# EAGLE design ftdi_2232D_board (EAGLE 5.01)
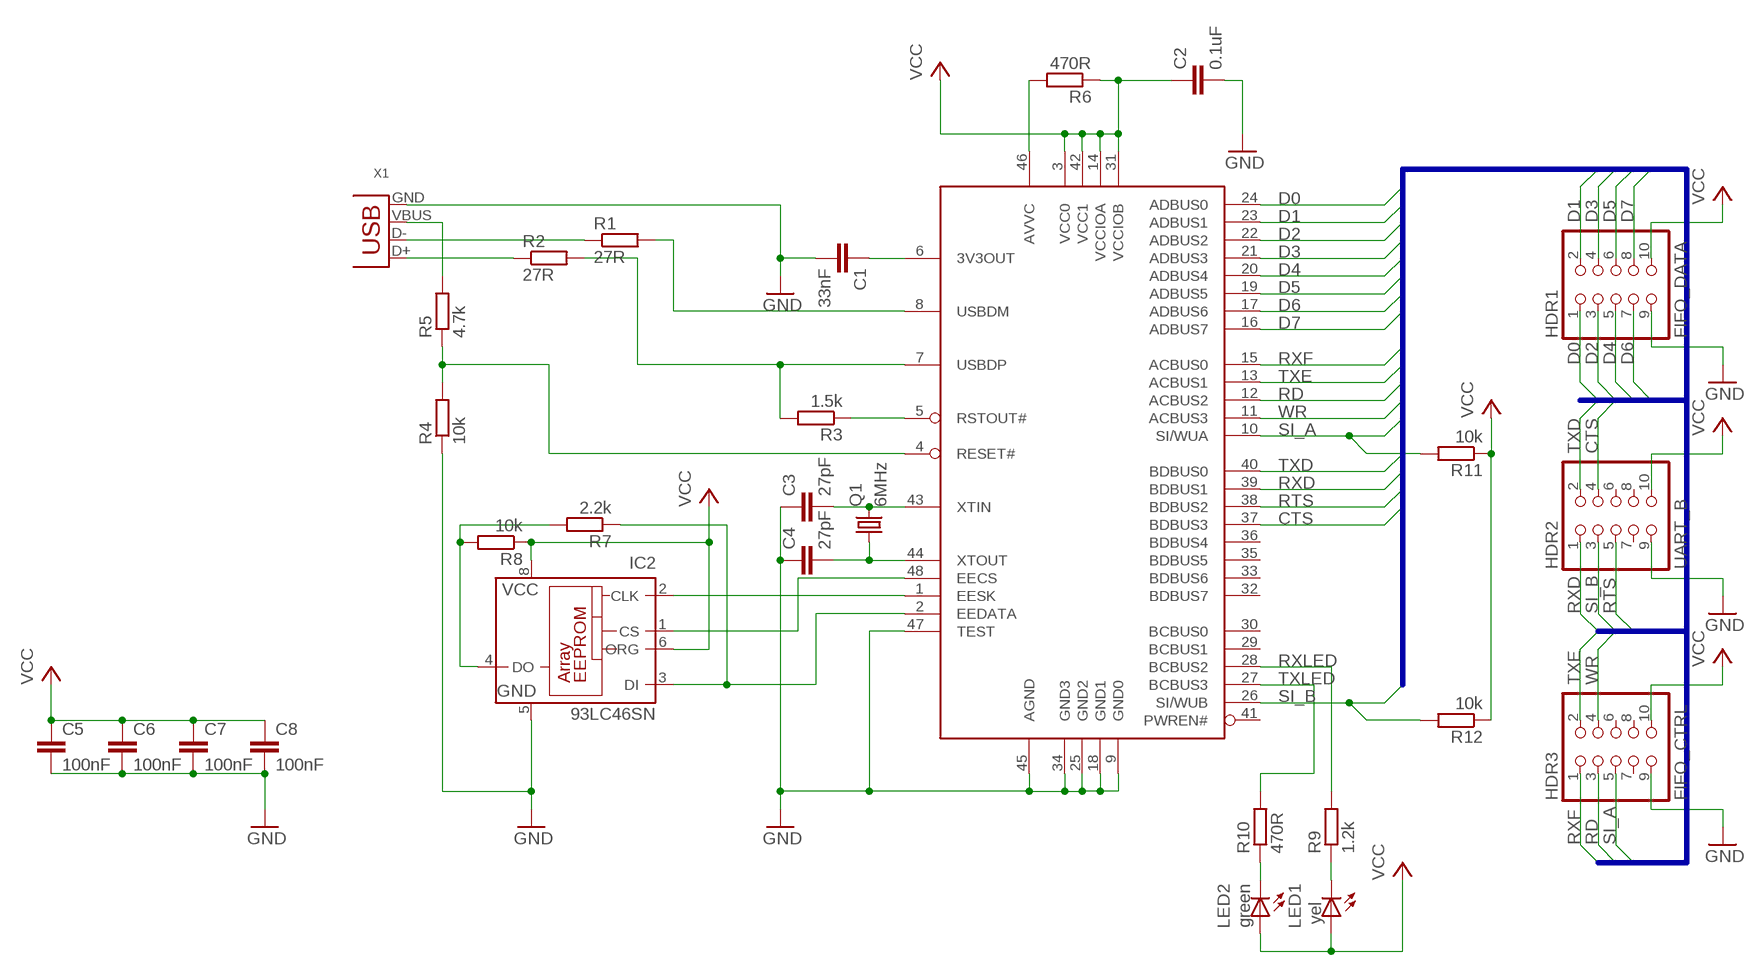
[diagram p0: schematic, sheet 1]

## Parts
C1  33nF  C-EUC0805  [C0805]
C2  0.1uF  C-EUC0805  [C0805]
C3  27pF  C-EUC0805  [C0805]
C4  27pF  C-EUC0805  [C0805]
C5  100nF  C-EUC0805  [C0805]
C6  100nF  C-EUC0805  [C0805]
C7  100nF  C-EUC0805  [C0805]
C8  100nF  C-EUC0805  [C0805]
HDR1  FIFO_DATA  PINHD-2X5  [2X05]
HDR2  UART_B  PINHD-2X5  [2X05]
HDR3  FIFO_CTRL  PINHD-2X5  [2X05]
IC1  FT2232D  FT2232L  [LQFP48]
IC2  93LC46SN  [SO-08]
LED1  yel  LEDSMT1206  [1206]
LED2  green  LEDSMT1206  [1206]
Q1  6MHz  CRYSTALHC49U70  [HC49U70]
R1  27R  R-EU_R0805  [R0805]
R2  27R  R-EU_R0805  [R0805]
R3  1.5k  R-EU_R0805  [R0805]
R4  10k  R-EU_R0805  [R0805]
R5  4.7k  R-EU_R0805  [R0805]
R6  470R  R-EU_R0805  [R0805]
R7  2.2k  R-EU_R0805  [R0805]
R8  10k  R-EU_R0805  [R0805]
R9  1.2k  R-EU_R0805  [R0805]
R10  470R  R-EU_R0805  [R0805]
R11  10k  R-EU_R0805  [R0805]
R12  10k  R-EU_R0805  [R0805]
X1  USBCON  USB-MB-S  [USB-MB-S]

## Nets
3V3OUT: C1.1 IC1.6(3V3OUT)
CTS: HDR2.4 IC1.37(BDBUS3)
D0: HDR1.1 IC1.24(ADBUS0)
D1: HDR1.2 IC1.23(ADBUS1)
D2: HDR1.3 IC1.22(ADBUS2)
D3: HDR1.4 IC1.21(ADBUS3)
D4: HDR1.5 IC1.20(ADBUS4)
D5: HDR1.6 IC1.19(ADBUS5)
D6: HDR1.7 IC1.17(ADBUS6)
D7: HDR1.8 IC1.16(ADBUS7)
D+: R2.1 X1.D+
D-: R1.1 X1.D-
EE_DOUT: IC2.4(DO) R7.2 R8.2
EECS: IC1.48(EECS) IC2.1(CS)
EEDATA: IC1.2(EEDATA) IC2.3(DI) R7.1
EESK: IC1.1(EESK) IC2.2(CLK)
GND: C1.2 C2.2 C3.1 C4.1 C5.2 C6.2 C7.2 C8.2 HDR1.9 HDR2.9 HDR3.9 IC1.9(GND0) IC1.18(GND1) IC1.25(GND2) IC1.34(GND3) IC1.45(AGND) IC1.47(TEST) IC2.5(GND) R4.1 X1.GND
N$12: IC1.46(AVVC) R6.2
N$13: LED1.C R9.1
N$14: LED2.C R10.1
RD: HDR3.3 IC1.12(ACBUS2)
RESET: IC1.4(RESET#) R4.2 R5.1
RSTOUT: IC1.5(RSTOUT#) R3.1
RTS: HDR2.5 IC1.38(BDBUS2)
RXD: HDR2.1 IC1.39(BDBUS1)
RXF: HDR3.1 IC1.15(ACBUS0)
RXLED: IC1.28(BCBUS2) R9.2
SI_A: HDR3.5 IC1.10(SI/WUA) R11.2
SI_B: HDR2.3 IC1.26(SI/WUB) R12.2
TXD: HDR2.2 IC1.40(BDBUS0)
TXE: HDR3.2 IC1.13(ACBUS1)
TXLED: IC1.27(BCBUS3) R10.2
USBDM: IC1.8(USBDM) R1.2
USBDP: IC1.7(USBDP) R2.2 R3.2
VBUS: R5.2 X1.VBUS
VCC: C2.1 C5.1 C6.1 C7.1 C8.1 HDR1.10 HDR2.10 HDR3.10 IC1.3(VCC0) IC1.14(VCCIOA) IC1.31(VCCIOB) IC1.42(VCC1) IC2.6(ORG) IC2.8(VCC) LED1.A LED2.A R6.1 R8.1 R11.1 R12.1
WR: HDR3.4 IC1.11(ACBUS3)
XTIN: C3.2 IC1.43(XTIN) Q1.2
XTOUT: C4.2 IC1.44(XTOUT) Q1.1
Unconnected: HDR2.6 HDR2.7 HDR2.8 HDR3.6 HDR3.7 HDR3.8 IC1.29(BCBUS1) IC1.30(BCBUS0) IC1.32(BDBUS7) IC1.33(BDBUS6) IC1.35(BDBUS5) IC1.36(BDBUS4) IC1.41(PWREN#) IC2.7(NU)

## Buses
D[0..7],RXF,TXE,RD,WR,SI_A,TXD,RXD,RTS,CTS,SI_B

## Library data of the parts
C1-C8 = rcl:C-EU: CAPACITOR, European symbol
HDR1-HDR3 = pinhead:PINHD-2X5: PIN HEADER
IC1 = ftdichip-3:FT2232L: USB UART / FIFO Controller 3nd Generation USB Double-UART (USB <-> Serial) - FIFO Controller
IC2 = microchip:93*: Serial EPROM 1 K/2 K/4 K, low voltage, Microwire
LED1 LED2 = led:LED: LED
Q1 = crystal:CRYSTAL: CRYSTAL
R1-R12 = rcl:R-EU_: RESISTOR, European symbol
X1 = con-usb-3:USB: USB Connectors

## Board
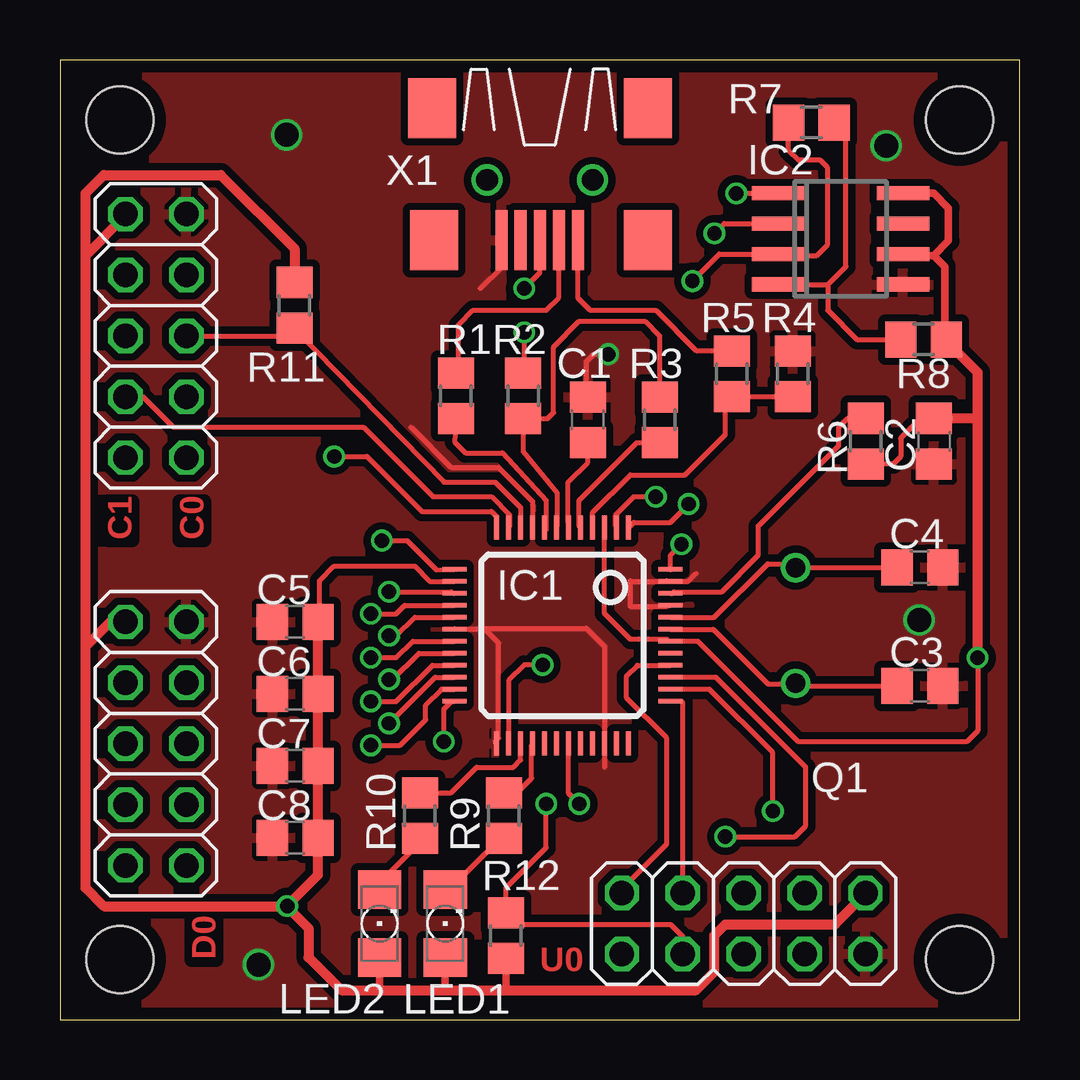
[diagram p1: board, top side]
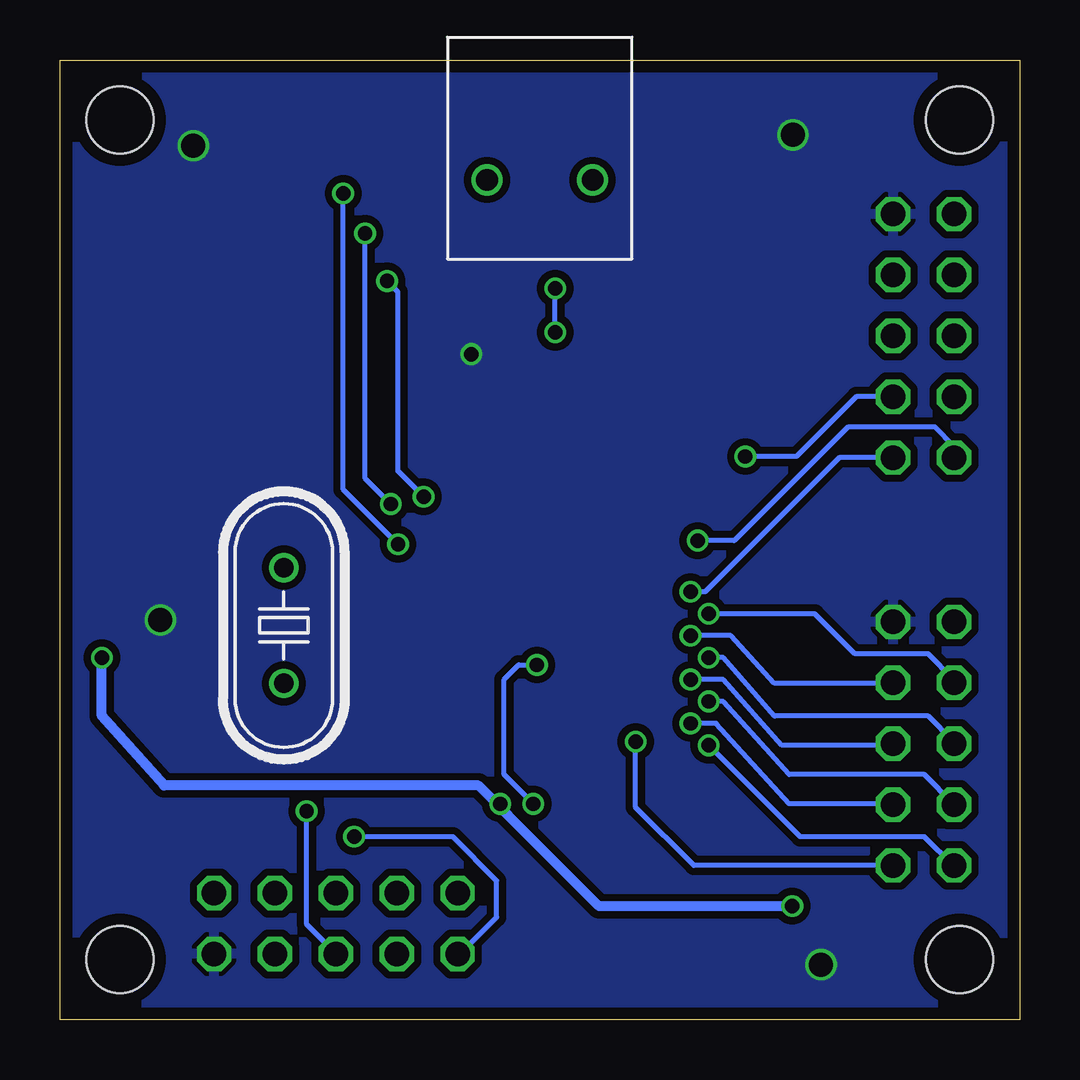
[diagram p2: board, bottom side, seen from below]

Size 40 x 40 mm. Coordinates in mm from the lower left corner, seen from the top.
Outline: 0,0 40,0 40,40 0,40 0,0
Copper layers (1*16): Top 0.035mm / dielectric 1.5mm / Bottom 0.035mm
Design rules "PCB-POOL *": minimum track width 6mil, minimum drill 12mil, track to track 8mil, track to pad 8mil, pad to pad 8mil, via to via 8mil, smd to smd 6mil, copper to edge 20mil, drill to drill 8mil, minimum pad ring 8mil, minimum via ring 6mil, stop-mask expansion 3mil, vias tented up to drill 0mil, thermal gap 8mil
Holes 2.8 mm at 2.5,37.5 37.5,37.5 37.5,2.5 2.5,2.5

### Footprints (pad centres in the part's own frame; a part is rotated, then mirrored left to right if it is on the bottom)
C0805 = smd 1.3 x 1.5: 1 -0.95,0; 2 0.95,0
2X05 = drill 1.016 octagon: 1 -5.08,-1.27; 2 -5.08,1.27; 3 -2.54,-1.27; 4 -2.54,1.27; 5 0,-1.27; 6 0,1.27; 7 2.54,-1.27; 8 2.54,1.27; 9 5.08,-1.27; 10 5.08,1.27
LQFP48 = smd 0.2 x 1: 1 -2.75,-4.5; 2 -2.25,-4.5; 3 -1.75,-4.5; 4 -1.25,-4.5; 5 -0.75,-4.5; 6 -0.25,-4.5; 7 0.25,-4.5; 8 0.75,-4.5; 9 1.25,-4.5; 10 1.75,-4.5; 11 2.25,-4.5; 12 2.75,-4.5; 25 2.75,4.5; 26 2.25,4.5; 27 1.75,4.5; 28 1.25,4.5; 29 0.75,4.5; 30 0.25,4.5; 31 -0.25,4.5; 32 -0.75,4.5; 33 -1.25,4.5; 34 -1.75,4.5; 35 -2.25,4.5; 36 -2.75,4.5 | smd 1 x 0.2: 13 4.5,-2.75; 14 4.5,-2.25; 15 4.5,-1.75; 16 4.5,-1.25; 17 4.5,-0.75; 18 4.5,-0.25; 19 4.5,0.25; 20 4.5,0.75; 21 4.5,1.25; 22 4.5,1.75; 23 4.5,2.25; 24 4.5,2.75; 37 -4.5,2.75; 38 -4.5,2.25; 39 -4.5,1.75; 40 -4.5,1.25; 41 -4.5,0.75; 42 -4.5,0.25; 43 -4.5,-0.25; 44 -4.5,-0.75; 45 -4.5,-1.25; 46 -4.5,-1.75; 47 -4.5,-2.25; 48 -4.5,-2.75
SO-08 = smd 0.6 x 2.2: 1 -1.905,-2.6; 2 -0.635,-2.6; 3 0.635,-2.6; 4 1.905,-2.6; 5 1.905,2.6; 6 0.635,2.6; 7 -0.635,2.6; 8 -1.905,2.6
1206 = smd 1.6 x 1.803: A -1.422,0; C 1.422,0
HC49U70 = drill 0.813 round: 1 -2.413,0; 2 2.413,0
R0805 = smd 1.3 x 1.5: 1 -0.95,0; 2 0.95,0
USB-MB-S = smd 2.5 x 0.5: D+ 2.5,0; D- 2.5,0.8; GND 2.5,-1.6; ID 2.5,-0.8; VBUS 2.5,1.6 | smd 2.5 x 2: P$1 -3,-4.5; P$2 -3,4.5; P$3 2.5,-4.4; P$4 2.5,4.5 | drill 0.9 round: P$5 0,2.2; P$6 0,-2.2

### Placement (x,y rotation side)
C1  22,25 90 top
C2  36.43,24.11 270 top
C3  35.85,13.91 180 top
C4  35.85,18.85 180 top
C5  9.8,16.58 180 top
C6  9.8,13.58 180 top
C7  9.8,10.58 180 top
C8  9.8,7.58 180 top
HDR1  4,11.5 90 top
HDR2  28.5,4 0 top
HDR3  4,28.5 90 top
IC1  20.95,16.02 180 top
IC2  32.54,32.54 270 top
LED1  16.06,4 90 top
LED2  13.32,4 90 top
Q1  30.67,16.42 270 bottom
R1  16.5,26 270 top
R2  19.3,26 270 top
R3  25,25 90 top
R4  30.54,26.91 270 top
R5  28,26.91 90 top
R6  33.59,24.11 90 top
R7  31.32,37.39 0 top
R8  36,28.35 180 top
R9  18.5,8.5 90 top
R10  15,8.5 90 top
R11  9.77,29.78 270 top
R12  18.59,3.5 90 top
X1  20,35 270 top

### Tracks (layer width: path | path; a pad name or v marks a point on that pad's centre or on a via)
3V3OUT
  Top 0.203: C1.1 22,23.22 21.18,22.4 21.18,20.73 21.2,20.71 IC1.6
CTS
  Top 0.203: IC1.37 25.9,13.27 25.96,13.21 HDR2.4
D0  (via drill 0.6)
  Top 0.203: IC1.24 16.32,13.27 16,12.95 v16,11.58
  Bottom 0.203: HDR1.1 13.58,6.42 16,8.84 v16,11.58
D1  (via drill 0.6)
  Top 0.203: IC1.23 15.9,13.77 15.24,13.11 15.24,12.5 14.17,11.43 v12.95,11.43
  Bottom 0.203: v12.95,11.43 9.14,7.62 3.96,7.62 2.74,6.4 HDR1.2
D2  (via drill 0.6)
  Top 0.203: IC1.22 15.64,14.27 v13.72,12.34
  Bottom 0.203: v13.72,12.34 12.65,12.34 9.6,8.99 5.33,8.99 5.3,8.96 HDR1.3
D3  (via drill 0.6)
  Top 0.203: IC1.21 15.53,14.77 14.02,13.26 v12.95,13.26
  Bottom 0.203: HDR1.4 2.73,8.98 3.96,10.21 9.6,10.21 12.34,13.26 v12.95,13.26
D4  (via drill 0.6)
  Top 0.203: IC1.20 14.96,15.27 13.87,14.17 v13.72,14.17
  Bottom 0.203: v13.72,14.17 12.34,14.17 9.91,11.43 5.33,11.43 HDR1.5
D5  (via drill 0.6)
  Top 0.203: IC1.19 14.7,15.77 14.02,15.09 v12.95,15.09
  Bottom 0.203: v12.95,15.09 12.34,15.09 10.21,12.65 3.81,12.65 2.73,11.57 HDR1.6
D6  (via drill 0.6)
  Top 0.203: IC1.17 14.79,16.77 14.02,16 v13.72,16
  Bottom 0.203: v13.72,16 12.04,16 10.21,14.02 5.33,14.02 5.32,14.04 HDR1.7
D7  (via drill 0.6)
  Top 0.203: IC1.16 14.37,17.27 14.02,16.92 v12.95,16.92
  Bottom 0.203: v12.95,16.92 8.53,16.92 6.86,15.24 3.81,15.24 2.73,14.16 HDR1.8
D+  (via drill 0.6)
  Top 0.203: R2.1 19.33,26.95 19.36,26.98 v19.36,28.65 | X1.D+ 20,31.12 v19.36,30.48
  Bottom 0.203: v19.36,28.65 v19.36,30.48
D-
  Top 0.203: X1.D- 20.8,30.1 20.27,29.57 17.22,29.57 16.61,28.96 16.61,26.98 16.59,26.95 R1.1
EE_DOUT
  Top 0.203: R7.2 32.27,37.22 32.77,36.73 32.77,31.39 32,30.63 | IC2.4 30.17,30.64 30.18,30.63 32,30.63 | R8.2 33.22,28.35 32,29.57 32,30.63
EECS  (via drill 0.6)
  Top 0.203: v25.91,19.81 25.45,19.36 25.45,18.75 IC1.48 | IC2.1 29.88,34.45 29.87,34.44 v28.19,34.44
  Bottom 0.203: v28.19,34.44 28.19,22.1 v25.91,19.81
EEDATA  (via drill 0.6)
  Top 0.203: v24.84,21.79 23.93,21.79 23.16,21.03 23.16,20.57 23.2,20.54 IC1.2 | v26.36,30.79 27.49,31.91 IC2.3 30.27,31.91 30.33,31.85 31.55,31.85 32,32.31 32,35.51 31.7,35.81 30.79,35.81 30.37,36.23 R7.1
  Bottom 0.203: v26.36,30.79 25.91,30.33 25.91,22.86 v24.84,21.79
EESK  (via drill 0.6)
  Top 0.203: v26.21,21.49 25.45,20.73 23.93,20.73 23.72,20.52 IC1.1 | IC2.2 27.69,33.18 v27.28,32.77
  Bottom 0.203: v26.21,21.49 27.13,22.4 27.28,22.55 v27.28,32.77
GND  (via drill 0.6, 1)
  Top 0.203: 25.3,18.29 25.32,18.27 IC1.47 | X1.GND 18.4,31.35 17.53,30.48 | v22.86,27.74 22.25,27.74 21.95,27.43 21.95,26.06 22,26.01 C1.2 | IC1.34 | IC1.9 19.7,21.6 18.29,23.01 16.31,23.01 14.63,24.69 | IC1.47 26.19,18.27 26.52,18.59 | IC1.47 23.79,18.27 23.77,18.29 23.77,17.22 25.3,17.22 25.34,17.27 IC1.45 | 17.68,16.27 17.72,16.27 18.29,15.7 18.29,11.73 18.14,11.58 IC1.25 | 17.68,16.27 IC1.18 16.45,16.3 | 17.68,16.27 17.68,16.31 21.95,16.31 22.7,15.55 IC1.34 | IC1.34 22.7,10.53 22.71,10.52 22.71,11.73 22.7,11.73 IC1.34
  other vias: 34.44,36.42 9.45,36.88 35.81,16.65 8.27,2.29
  pour Top (isolate 0.305): -1.98,41.91 42.21,41.91 42.21,-2.29 -2.29,-2.29 -2.29,41.91
  pour Bottom (isolate 0.305): -1.07,40.84 40.84,40.84 40.84,-0.91 -1.07,-0.91
N$12
  Top 0.203: R6.2 32.83,25.06 32.46,24.69 32.46,23.93 29.11,20.57 29.11,19.36 27.58,17.83 25.6,17.83 25.54,17.77 IC1.46
N$13
  Top 0.203: R9.1 18.37,7.55 16.24,5.42 LED1.C
N$14
  Top 0.203: R10.1 15,7.38 13.32,5.7 LED2.C
RD  (via drill 0.6)
  Top 0.203: IC1.12 18.2,20.97 17.98,21.18 15.09,21.18 12.8,23.47 v11.43,23.47
  Bottom 0.203: HDR3.3 6.81,25.96 9.3,23.47 v11.43,23.47
RESET
  Top 0.203: IC1.4 22.2,21.13 23.77,22.71 26.06,22.71 27.74,24.38 27.74,25.76 27.95,25.96 R5.1 30.58,25.96 | 30.58,25.96 R4.2 | 30.58,25.96 30.63,25.91
RSTOUT
  Top 0.203: R3.1 24.05,24.05 21.64,21.64 21.64,20.57 IC1.5
RTS  (via drill 0.6)
  Top 0.203: v29.72,8.69 29.72,10.36 | 29.72,10.36 29.72,10.52 | IC1.38 27.07,13.77 29.72,11.12 29.72,10.36
  Bottom 0.203: HDR2.5 28.5,2.74 29.72,3.96 v29.72,8.69
RXD  (via drill 0.6)
  Top 0.203: IC1.39 27.34,14.27 31.09,10.52 31.09,8.08 30.63,7.62 v27.74,7.62
  Bottom 0.203: v27.74,7.62 23.62,7.62 21.79,5.79 21.79,4.27 23.42,2.64 | 23.42,2.64 23.47,2.59 | 23.42,2.64 HDR2.1
RXF  (via drill 0.6)
  Top 0.203: IC1.15 16.4,17.77 16.31,17.83 v13.72,17.83
  Bottom 0.203: HDR3.1 7.52,23.42 13.11,17.83 v13.72,17.83
RXLED
  Top 0.203: R9.2 19.05,9.45 19.66,10.06 19.66,11.43 19.7,11.47 IC1.28
SI_A
  Top 0.203: HDR3.5 9.45,28.5 9.75,28.8 | IC1.10 19.2,21.34 18.14,22.4 16,22.4 9.75,28.8 | 9.75,28.8 R11.2
SI_B  (via drill 0.6)
  Top 0.203: IC1.26 18.7,14.13 19.36,14.78 v20.12,14.78 | HDR2.3 25.96,3.45 25.45,3.96 19.2,3.96 18.71,4.45 R12.2 | 18.59,4.42 18.59,4.43 R12.2 | R12.2 18.59,5.48 20.27,7.16 v20.27,8.99
  Bottom 0.203: v20.12,14.78 20.88,14.78 21.49,14.17 21.49,10.21 v20.27,8.99
TXD
  Top 0.203: IC1.40 24.06,14.77 23.62,14.33 23.62,13.41 25.3,11.73 25.3,7.32 23.32,5.33 23.38,5.27 HDR2.2
TXE  (via drill 0.6)
  Top 0.203: IC1.13 16.33,18.77 15.7,18.75 14.48,19.96 v13.41,19.96
  Bottom 0.203: HDR3.2 2.73,23.91 3.5,24.69 7.16,24.69 11.89,19.96 v13.41,19.96
TXLED
  Top 0.203: R10.2 16.31,9.45 17.37,10.52 18.9,10.52 19.2,10.82 19.2,11.43 IC1.27
USBDM
  Top 0.203: R1.2 16.46,24.08 16.92,23.62 18.44,23.62 20.27,21.64 20.27,20.42 20.2,20.49 IC1.8
USBDP
  Top 0.203: IC1.7 20.7,20.55 20.73,20.57 20.73,21.95 19.3,23.67 R2.2 20.33,25.05 20.57,25.3 20.57,28.04 21.64,29.11 24.38,29.11 24.99,28.5 24.99,26.06 25,26.05 R3.2
VBUS
  Top 0.203: X1.VBUS 21.6,30.06 22.1,29.57 24.84,29.57 26.52,27.89 27.89,27.89 27.91,27.86 R5.2
VCC  (via drill 0.6)
  Top 0.203: IC1.42 26.6,15.77 30.79,11.58 37.8,11.58 38.25,12.04 v38.25,15.09 | IC1.42 25.37,15.77 | IC1.3 22.7,16.93 23.77,15.85 25.3,15.85 25.38,15.77 IC1.42 | IC1.14 15.41,18.27 14.78,18.9 11.43,18.9 10.82,18.29 10.82,16.76 10.76,16.7 C5.1 | R6.1 34.74,23.16 35.05,23.47 35.05,24.23 35.97,25.15 36.05,25.06 C2.1 | IC1.31 21.2,9.43 v21.64,8.99
  Top 0.305: LED2.A 13.32,1.28 13.26,1.22 | LED1.A 16.06,1.28 16,1.22 | R12.1 18.59,1.23 18.59,1.22 | IC2.8 36.42,34.45 37.03,33.83 37.03,32.46 36.42,31.85 | IC2.6 35.3,31.91 35.36,31.85 36.42,31.85 | 36.88,28.35 36.88,31.39 36.42,31.85
  Top 0.406: HDR1.10 2.1,16.58 1.07,15.54 | 1.07,15.54 1.07,5.49 1.83,4.72 9.45,4.72 | HDR3.10 2.73,33.54 2.74,33.53 1.07,31.85 1.07,31.7 | 1.07,15.54 1.07,31.7 | R11.1 9.77,32.14 6.71,35.2 1.83,35.2 1.07,34.44 1.07,31.7 | 9.45,4.72 10.76,6.03 C8.1 10.76,10.45 10.82,10.52 C7.1 10.76,13.5 10.82,13.56 10.8,13.58 C6.1 10.76,13.63 10.67,13.72 10.76,13.8 C5.1 | R8.1 36.88,28.35 38.25,26.98 38.25,24.99 | v38.25,15.09 38.25,24.99 | C2.1 38.19,25.06 38.25,24.99 | HDR2.10 33.58,5.23 32.31,3.96 27.74,3.96 27.28,3.5 27.28,1.98 26.52,1.22 18.59,1.22 16,1.22 13.26,1.22 11.73,1.22 10.36,2.59 10.36,3.81 9.45,4.72 | 9.45,4.72 v9.47,4.72
  Bottom 0.203: v21.64,8.99 21.64,8.84 21.34,8.53
  Bottom 0.406: v38.25,15.09 38.25,12.65 35.66,9.75 22.55,9.75 21.34,8.53 17.53,4.72 v9.47,4.72
WR
  Top 0.203: HDR3.4 3.45,25.96 4.72,24.69 12.65,24.69 15.54,21.79 17.98,21.79 18.75,21.03 18.75,20.57 IC1.11
XTIN
  Top 0.203: IC1.43 27.23,16.27 29.5,14 30.5,14 | 30.5,14 30.51,14.01 Q1.2 | C3.2 30.59,13.91 30.5,14
XTOUT
  Top 0.203: IC1.44 27.27,16.77 29.5,19 30.5,19 | 30.5,19 Q1.1 | C4.2 30.65,18.85 30.5,19

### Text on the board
Top: C1 | C0 | D0 | U0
